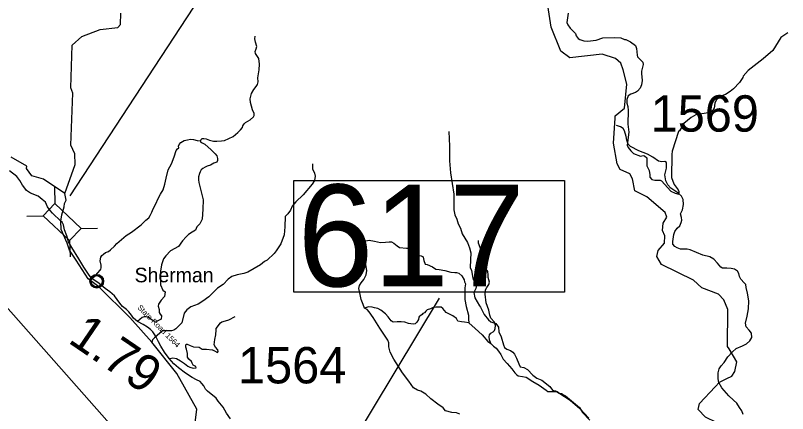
# Model space of a CAD drawing. Extents: x 1248089 to 1457196, y 820910 to 988753.
# Drawn here: x 1308265 to 1318874, y 948203 to 953678 of the extents above; entities that cross this region are included whole.
import ezdxf

# ---------------------------------------------------------------- set-up
doc = ezdxf.new("R2010")
doc.units = 0
for name, color, linetype in [('Exist Civil Demographics Community CELL', 7, 'Continuous'), ('Exist Civil Demographics Community Label', 7, 'Continuous'), ('Exist Hydrographic Creek Single Shore', 7, 'Continuous'), ('Exist Hydrographic Misc Water Feature', 7, 'Continuous'), ('Exist Road Non-System Type 51', 7, 'Continuous'), ('Exist Road Secondary Structure Standard Bridge CELL', 7, 'Continuous'), ('Exist Road Secondary Structure Standard Bridge Number Label', 7, 'Continuous'), ('Exist Road Secondary Type 10 Attributed', 7, 'Continuous'), ('Exist Road Secondary Type 51 Attributed', 7, 'Continuous'), ('Exist Road Secondary Type 51 Label', 7, 'Continuous'), ('Prop GRAU CAT1 Cell', 7, 'Continuous'), ('Prop Lane Lines', 7, 'Continuous')]:
    doc.layers.add(name, color=color, linetype=linetype)

msp = doc.modelspace()

# ---------------------------------------------------------------- linework, layer by layer
at = {"layer": 'Exist Civil Demographics Community CELL'}
msp.add_lwpolyline([(1309304, 950035), (1309305, 950041), (1309307, 950047), (1309310, 950055), (1309313, 950060), (1309316, 950066), (1309320, 950071), (1309324, 950075), (1309328, 950080), (1309334, 950085), (1309339, 950088), (1309344, 950091), (1309349, 950094), (1309355, 950096), (1309360, 950098), (1309365, 950099), (1309369, 950100), (1309374, 950100), (1309380, 950101), (1309384, 950101), (1309390, 950100), (1309395, 950100), (1309400, 950099), (1309405, 950097), (1309410, 950095), (1309417, 950092), (1309423, 950089), (1309428, 950085), (1309433, 950081), (1309436, 950078), (1309441, 950074), (1309444, 950069), (1309448, 950064), (1309451, 950059), (1309453, 950054), (1309455, 950049), (1309457, 950044), (1309458, 950040), (1309459, 950034), (1309460, 950029), (1309460, 950023), (1309460, 950017), (1309459, 950011), (1309458, 950006), (1309457, 950000), (1309455, 949994), (1309452, 949989), (1309449, 949983), (1309446, 949978), (1309443, 949973), (1309438, 949968), (1309433, 949963), (1309428, 949959), (1309423, 949956), (1309419, 949953), (1309412, 949950), (1309405, 949947), (1309399, 949946), (1309392, 949944), (1309388, 949944), (1309383, 949944), (1309378, 949944), (1309373, 949944), (1309368, 949945), (1309362, 949946), (1309357, 949947), (1309352, 949949), (1309347, 949951), (1309344, 949954), (1309337, 949958), (1309331, 949962), (1309326, 949966), (1309322, 949971), (1309319, 949975), (1309316, 949979), (1309312, 949986), (1309310, 949990), (1309308, 949994), (1309306, 950002), (1309304, 950009), (1309303, 950014), (1309303, 950021), (1309303, 950025), (1309303, 950032)], close=True, dxfattribs=at)
for centre, radius in [((1309382, 950023), 94.3), ((1309381, 950023), 76.7)]:
    msp.add_circle(centre, radius, dxfattribs=at)
at = {"layer": 'Exist Hydrographic Creek Single Shore'}
for points in [[(1316504, 952267), (1316507, 952297), (1316634, 952403), (1316667, 952733), (1316613, 952928), (1316582, 953021), (1316508, 953088), (1316326, 953144), (1315883, 953094), (1315759, 953188), (1315625, 953519), (1315560, 953937)], [(1318070, 949093), (1318051, 949124), (1318054, 949633), (1317999, 949769), (1317926, 949845), (1317694, 949932), (1317580, 950036), (1317143, 950255), (1317079, 950365), (1317097, 950446), (1317183, 950547), (1317186, 950645), (1317154, 950721), (1317164, 950823), (1317217, 950904), (1317193, 950970), (1316939, 951185), (1316775, 951264), (1316745, 951432), (1316705, 951498), (1316573, 951560), (1316533, 951636), (1316481, 951923), (1316504, 952267)], [(1308944, 951228), (1308649, 951428), (1308492, 951473), (1308419, 951573), (1308420, 951606), (1308206, 951729)], [(1308887, 950849), (1308902, 950934), (1308935, 951044), (1308941, 951092), (1308964, 951139), (1308944, 951228)], [(1309262, 950054), (1309098, 950312), (1309007, 950452), (1308974, 950547), (1308892, 950733), (1308887, 950849)], [(1311047, 947831), (1310858, 948058), (1310733, 948077), (1310757, 948262), (1310481, 948756), (1310139, 949185), (1309835, 949522), (1309411, 949947), (1309262, 950054)], [(1317921, 947117), (1317896, 947134), (1317947, 947534), (1318087, 947807), (1318114, 947915), (1318050, 948008), (1317745, 948155), (1317647, 948259), (1317665, 948340), (1317879, 948570), (1317939, 948634), (1318041, 948683), (1318108, 948716), (1318151, 948781), (1318179, 948915), (1318070, 949093)]]:
    msp.add_lwpolyline(points, dxfattribs=at)
at = {"layer": 'Exist Hydrographic Misc Water Feature'}
for points in [[(1308944, 951228), (1309087, 951626), (1309082, 951773), (1309027, 951893), (1309052, 952611), (1309028, 952684), (1309042, 953268), (1309178, 953390), (1309431, 953483), (1309673, 953511), (1309707, 953553), (1309711, 953711)], [(1315858, 953711), (1315841, 953580), (1315853, 953548), (1315888, 953503), (1315962, 953429), (1315969, 953397), (1315998, 953360), (1316018, 953347), (1316074, 953330), (1316126, 953323), (1316246, 953340), (1316337, 953372), (1316501, 953376), (1316581, 953370), (1316635, 953347), (1316654, 953346), (1316718, 953317), (1316785, 953263), (1316800, 953223), (1316806, 953134), (1316811, 953111), (1316885, 953037), (1316889, 953005), (1316867, 952913), (1316866, 952881), (1316877, 952783), (1316868, 952723), (1316851, 952676), (1316814, 952636), (1316786, 952617), (1316719, 952595), (1316686, 952573), (1316665, 952522), (1316664, 952473), (1316679, 952425), (1316686, 952373), (1316679, 952181), (1316691, 952071), (1316671, 951895), (1316686, 951862), (1316719, 951818), (1316758, 951781), (1316853, 951742), (1316890, 951752), (1316909, 951747), (1316941, 951718), (1316942, 951608), (1316971, 951544), (1316981, 951484), (1316981, 951452), (1317008, 951422), (1317052, 951412), (1317124, 951414), (1317144, 951402), (1317271, 951263), (1317330, 951233), (1317382, 951220)], [(1318880, 953438), (1318783, 953373), (1318673, 953197), (1318540, 953082), (1318332, 952921), (1318266, 952844), (1318260, 952826), (1318214, 952756), (1318132, 952671), (1318087, 952633), (1318020, 952592), (1317959, 952566), (1317902, 952521), (1317898, 952522), (1317873, 952471), (1317867, 952403), (1317847, 952370), (1317820, 952347), (1317756, 952332), (1317667, 952322), (1317615, 952309), (1317550, 952275), (1317448, 952193), (1317388, 952093), (1317376, 952081), (1317287, 951813), (1317282, 951765), (1317281, 951451), (1317296, 951398), (1317315, 951354), (1317371, 951282), (1317382, 951258), (1317382, 951220)], [(1314219, 952081), (1314228, 951879), (1314227, 951679), (1314242, 951514), (1314289, 951220), (1314290, 951003), (1314304, 950934), (1314329, 950878), (1314347, 950814), (1314378, 950752), (1314404, 950676), (1314475, 950554), (1314506, 950481), (1314524, 950413), (1314516, 950315), (1314514, 950211), (1314529, 950171), (1314548, 950066), (1314556, 950046), (1314583, 950010), (1314598, 949965), (1314593, 949922), (1314562, 949870), (1314576, 949795), (1314641, 949684), (1314657, 949668), (1314705, 949566), (1314763, 949493), (1314798, 949464), (1314866, 949443), (1314901, 949389), (1314909, 949325), (1314940, 949260), (1314969, 949147), (1314986, 949112), (1315018, 949087), (1315065, 949069), (1315101, 949049), (1315124, 949020), (1315151, 948967), (1315181, 948887), (1315202, 948846), (1315250, 948837), (1315301, 948808), (1315372, 948732), (1315431, 948691), (1315498, 948661), (1315606, 948575), (1315645, 948526), (1315685, 948517), (1315736, 948485), (1315768, 948479)], [(1314219, 952081), (1314228, 951879), (1314227, 951679), (1314242, 951514), (1314289, 951220), (1314290, 951003), (1314304, 950934), (1314329, 950878), (1314347, 950814), (1314378, 950752), (1314404, 950676), (1314475, 950554), (1314506, 950481), (1314524, 950413), (1314516, 950315), (1314514, 950211), (1314529, 950171), (1314548, 950066), (1314556, 950046), (1314583, 950010), (1314598, 949965), (1314593, 949922), (1314562, 949870), (1314576, 949795), (1314641, 949684), (1314657, 949668), (1314705, 949566), (1314763, 949493), (1314798, 949464), (1314866, 949443), (1314901, 949389), (1314909, 949325), (1314940, 949260), (1314969, 949147), (1314986, 949112), (1315018, 949087), (1315065, 949069), (1315101, 949049), (1315124, 949020), (1315151, 948967), (1315181, 948887), (1315202, 948846), (1315250, 948837), (1315301, 948808), (1315372, 948732), (1315431, 948691), (1315498, 948661), (1315606, 948575), (1315645, 948526), (1315685, 948517), (1315736, 948485), (1315768, 948479)], [(1312348, 951637), (1312348, 951568), (1312375, 951510), (1312382, 951470), (1312372, 951406), (1312341, 951359), (1312218, 951212), (1312117, 951114), (1312068, 951054), (1312042, 950998), (1312009, 950951), (1311972, 950911), (1311967, 950773), (1311957, 950662), (1311912, 950539), (1311849, 950442), (1311820, 950403), (1311724, 950313), (1311688, 950296), (1311631, 950249), (1311460, 950147), (1311402, 950128), (1311313, 950110), (1311237, 950086), (1311188, 950051), (1311118, 949980), (1311041, 949928), (1310920, 949809), (1310838, 949747), (1310774, 949708), (1310677, 949669), (1310618, 949630), (1310585, 949583), (1310553, 949449), (1310469, 949367), (1310441, 949352), (1310409, 949343), (1310285, 949341), (1310174, 949246), (1310150, 949218), (1310139, 949185)], [(1315768, 948479), (1315776, 948476), (1315788, 948465), (1315823, 948447), (1316014, 948287), (1316056, 948218), (1316158, 948113)]]:
    msp.add_lwpolyline(points, dxfattribs=at)
at = {"layer": 'Exist Road Non-System Type 51'}
for points in [[(1310807, 951953), (1310811, 951969), (1310829, 951987), (1310855, 951987), (1310884, 951982), (1310933, 951963), (1310984, 951949), (1311031, 951948), (1311094, 951953), (1311137, 951958), (1311195, 951984), (1311258, 952014), (1311319, 952067), (1311356, 952103), (1311383, 952138), (1311391, 952159), (1311406, 952186), (1311427, 952208), (1311488, 952242), (1311537, 952284), (1311545, 952303), (1311545, 952331), (1311524, 952379), (1311495, 952482), (1311489, 952531), (1311508, 952603), (1311539, 952659), (1311571, 952702), (1311591, 952730), (1311600, 952763), (1311594, 952820), (1311606, 952874), (1311613, 952931), (1311618, 953009), (1311609, 953085), (1311564, 953155), (1311557, 953184), (1311571, 953221), (1311581, 953252), (1311565, 953310), (1311556, 953355), (1311557, 953395)], [(1309313, 950061), (1309330, 950069), (1309366, 950101), (1309427, 950173), (1309440, 950189), (1309444, 950207), (1309442, 950242), (1309431, 950303), (1309436, 950355), (1309451, 950377), (1309474, 950396), (1309503, 950416), (1309542, 950430), (1309572, 950454), (1309624, 950506), (1309658, 950542), (1309784, 950653), (1309861, 950697), (1309991, 950799), (1310056, 950861), (1310097, 950893), (1310118, 950926), (1310138, 950971), (1310158, 951020), (1310195, 951089), (1310228, 951162), (1310256, 951219), (1310293, 951280), (1310317, 951358), (1310338, 951439), (1310362, 951554), (1310407, 951639), (1310448, 951733), (1310472, 951819), (1310491, 951843), (1310510, 951858), (1310507, 951880), (1310515, 951904), (1310537, 951930), (1310560, 951946), (1310584, 951956), (1310628, 951967), (1310671, 951976), (1310712, 951973), (1310764, 951960), (1310807, 951953)], [(1310807, 951953), (1310808, 951942), (1310822, 951929), (1310869, 951908), (1310954, 951831), (1311008, 951777), (1311030, 951747), (1311039, 951710), (1311043, 951683), (1311030, 951661), (1310993, 951648), (1310944, 951618), (1310898, 951603), (1310871, 951592), (1310838, 951573), (1310819, 951557), (1310805, 951528), (1310795, 951504), (1310779, 951459), (1310779, 951419), (1310785, 951381), (1310846, 951144)], [(1310846, 951144), (1310840, 951012), (1310831, 950875), (1310797, 950814), (1310757, 950769), (1310737, 950724), (1310692, 950696), (1310643, 950667), (1310611, 950635), (1310562, 950578), (1310505, 950500), (1310395, 950439), (1310330, 950370), (1310301, 950329), (1310273, 950247), (1310260, 950162), (1310260, 950035), (1310260, 949974), (1310289, 949901), (1310321, 949876), (1310313, 949815), (1310269, 949762), (1310232, 949709), (1310228, 949678), (1310239, 949636), (1310241, 949591), (1310254, 949568), (1310270, 949547), (1310266, 949500), (1310259, 949497), (1310248, 949490), (1310205, 949470), (1310167, 949475), (1310117, 949506), (1310083, 949527), (1310055, 949532), (1310035, 949531), (1310004, 949524), (1309941, 949471)], [(1314371, 948197), (1314326, 948213), (1314263, 948217), (1314175, 948242), (1314143, 948283), (1314067, 948330), (1313972, 948407), (1313902, 948472), (1313837, 948511), (1313789, 948524), (1313735, 948556), (1313672, 948648), (1313584, 948761), (1313465, 948949), (1313415, 949049), (1313395, 949123), (1313395, 949177), (1313382, 949211), (1313271, 949378), (1313179, 949525), (1313127, 949602), (1313098, 949634), (1313062, 949654), (1313044, 949704), (1313017, 949772), (1312999, 949864), (1312983, 949925), (1312992, 949966), (1313014, 950002), (1313053, 950047), (1313082, 950110), (1313091, 950169), (1313077, 950275), (1313048, 950370), (1313028, 950399), (1313026, 950445), (1313026, 950477), (1313037, 950522), (1313059, 950558), (1313080, 950579), (1313125, 950588), (1313197, 950572), (1313280, 950556), (1313348, 950558), (1313398, 950563), (1313434, 950565), (1313465, 950545), (1313508, 950511), (1313542, 950486), (1313637, 950477), (1313695, 950477), (1313761, 950452)], [(1314796, 949167), (1314777, 949219), (1314775, 949256), (1314779, 949287), (1314799, 949307), (1314831, 949326), (1314847, 949346), (1314858, 949371), (1314863, 949414), (1314849, 949459), (1314797, 949517), (1314781, 949554), (1314770, 949626), (1314732, 949725), (1314721, 949847), (1314725, 949903), (1314743, 949937), (1314770, 949976), (1314777, 950012), (1314761, 950073), (1314759, 950109), (1314757, 950157), (1314734, 950190), (1314705, 950227), (1314687, 950274), (1314687, 950308), (1314689, 950362), (1314662, 950452), (1314626, 950547), (1314626, 950583)], [(1313761, 950452), (1313768, 950425), (1313786, 950400), (1313801, 950375), (1313838, 950373), (1313867, 950360), (1313869, 950353), (1313878, 950308), (1313896, 950256), (1313921, 950251), (1313995, 950220), (1314043, 950188), (1314088, 950186), (1314165, 950170), (1314248, 950147), (1314302, 950145), (1314327, 950145), (1314356, 950132), (1314397, 950098), (1314430, 950044), (1314436, 950015), (1314450, 949988), (1314441, 949932), (1314439, 949866), (1314441, 949771), (1314457, 949674), (1314488, 949555), (1314491, 949503), (1314495, 949453)], [(1314495, 949453), (1314436, 949458), (1314394, 949464), (1314344, 949473), (1314324, 949510), (1314274, 949546), (1314231, 949568), (1314182, 949595), (1314139, 949647), (1314116, 949665), (1314089, 949668), (1314048, 949665), (1313997, 949656), (1313967, 949645), (1313922, 949629), (1313902, 949613), (1313886, 949589), (1313861, 949580), (1313852, 949566), (1313836, 949550), (1313818, 949543), (1313807, 949528), (1313803, 949498), (1313780, 949460), (1313758, 949437), (1313728, 949433), (1313667, 949440), (1313615, 949462), (1313564, 949464), (1313509, 949464), (1313455, 949462), (1313427, 949479), (1313384, 949535), (1313348, 949576), (1313287, 949623), (1313244, 949650), (1313199, 949659), (1313167, 949666), (1313115, 949671), (1313062, 949654)], [(1310377, 948962), (1310408, 948964), (1310426, 948969), (1310479, 948960), (1310531, 948929), (1310586, 948892), (1310634, 948857), (1310663, 948841), (1310709, 948828), (1310746, 948833), (1310742, 948850), (1310707, 948868), (1310691, 948896), (1310683, 948921), (1310646, 948953), (1310628, 948977), (1310628, 949030), (1310613, 949089), (1310604, 949116), (1310604, 949136), (1310610, 949157), (1310624, 949158), (1310665, 949140), (1310713, 949122), (1310790, 949114), (1310830, 949090), (1310889, 949087), (1310968, 949079), (1310973, 949079), (1310999, 949068), (1311039, 949044), (1311052, 949056), (1311047, 949081), (1311012, 949116), (1310997, 949149), (1311006, 949221), (1311017, 949287), (1311021, 949355), (1311025, 949371), (1311041, 949397), (1311063, 949427), (1311083, 949450), (1311103, 949463), (1311151, 949476), (1311199, 949494), (1311283, 949538)], [(1314495, 949453), (1314581, 949373), (1314678, 949285), (1314755, 949192), (1314796, 949167)], [(1314796, 949167), (1314833, 949130), (1314869, 949103), (1314900, 949060), (1314934, 949015), (1314966, 948950), (1315022, 948891), (1315085, 948819), (1315128, 948762), (1315148, 948740), (1315173, 948724), (1315234, 948715), (1315281, 948704), (1315372, 948645), (1315462, 948595), (1315557, 948525), (1315581, 948507), (1315638, 948507), (1315710, 948505), (1315744, 948478), (1315886, 948388), (1316021, 948272), (1316143, 948142)]]:
    msp.add_lwpolyline(points, dxfattribs=at)
at = {"layer": 'Exist Road Secondary Structure Standard Bridge CELL'}
for p, q in [((1308801, 951318), (1308807, 951091)), ((1308421, 950918), (1308647, 950924)), ((1309165, 950749), (1309392, 950754)), ((1309009, 950585), (1309015, 950358))]:
    msp.add_line(p, q, dxfattribs=at)
msp.add_lwpolyline([(1308807, 951091), (1309166, 950749), (1309006, 950582), (1308647, 950924)], close=True, dxfattribs=at)
at = {"layer": 'Exist Road Secondary Structure Standard Bridge Number Label'}
msp.add_line((1309019, 951197), (1312285, 956192), dxfattribs=at)
for points in [[(1311436, 945141), (1311012, 946414), (1306982, 950975), (1306487, 954475)], [(1311311, 947403), (1311959, 947293), (1312875, 947766), (1314091, 949788)]]:
    msp.add_lwpolyline(points, dxfattribs=at)
msp.add_lwpolyline([(1312091, 951409), (1315807, 951409), (1315807, 949873), (1312091, 949873)], close=True, dxfattribs=at)
at = {"layer": 'Exist Road Secondary Type 10 Attributed'}
for points in [[(1318065, 948448), (1317973, 948557), (1317932, 948629), (1317919, 948679), (1317920, 948763), (1317935, 948819), (1317961, 948858), (1318005, 948904), (1318055, 948981), (1318116, 949054), (1318170, 949099), (1318256, 949135), (1318310, 949163), (1318355, 949204), (1318381, 949251), (1318379, 949307), (1318346, 949351), (1318307, 949394), (1318294, 949447), (1318317, 949544), (1318337, 949643), (1318340, 949753), (1318322, 949860), (1318304, 949936), (1318299, 949977), (1318276, 950002), (1318232, 950053), (1318216, 950086), (1318206, 950130), (1318187, 950161), (1318143, 950191), (1318099, 950199), (1318041, 950202), (1317979, 950203), (1317955, 950218), (1317912, 950273), (1317861, 950326), (1317804, 950358), (1317711, 950383), (1317537, 950456), (1317493, 950464), (1317403, 950464), (1317358, 950481), (1317323, 950502), (1317298, 950531), (1317300, 950570), (1317311, 950667), (1317326, 950709), (1317359, 950753), (1317394, 950787), (1317414, 950829), (1317423, 950862), (1317415, 950898), (1317402, 950950), (1317430, 951006), (1317443, 951077), (1317438, 951149), (1317418, 951191), (1317368, 951238), (1317268, 951302), (1317230, 951347), (1317203, 951405), (1317189, 951485), (1317209, 951578), (1317212, 951620), (1317209, 951655), (1317190, 951668), (1317146, 951667), (1317100, 951674), (1317021, 951728), (1316950, 951772), (1316831, 951816), (1316718, 951876), (1316684, 951910), (1316665, 951963), (1316658, 952015), (1316635, 952089), (1316616, 952122), (1316577, 952145), (1316524, 952163)], [(1318264, 948191), (1318244, 948240), (1318214, 948288), (1318176, 948346), (1318131, 948385), (1318065, 948448)]]:
    msp.add_lwpolyline(points, dxfattribs=at)
at = {"layer": 'Exist Road Secondary Type 51 Attributed'}
for points in [[(1308887, 950849), (1308772, 950958), (1308740, 950996), (1308706, 951047), (1308676, 951109), (1308634, 951145), (1308575, 951194), (1308473, 951236), (1308419, 951270), (1308393, 951302), (1308364, 951346), (1308324, 951410), (1308285, 951461), (1308184, 951541)], [(1311221, 948130), (1311166, 948210), (1311117, 948293), (1311052, 948374), (1311024, 948414), (1310994, 948439), (1310954, 948469), (1310903, 948509), (1310877, 948540), (1310855, 948586), (1310828, 948616), (1310802, 948644), (1310752, 948665), (1310694, 948697), (1310601, 948760), (1310504, 948834), (1310440, 948889), (1310377, 948962), (1310315, 949048), (1310261, 949132), (1310231, 949189), (1310189, 949274), (1310153, 949327), (1310119, 949361), (1310081, 949393), (1310022, 949427), (1309941, 949471), (1309889, 949517), (1309861, 949557), (1309823, 949604), (1309789, 949634), (1309734, 949676), (1309698, 949723), (1309662, 949771), (1309626, 949822), (1309561, 949877), (1309497, 949922), (1309414, 949990), (1309313, 950061), (1309277, 950108), (1309203, 950218), (1309135, 950330), (1309040, 950485), (1308994, 950564), (1308971, 950645), (1308941, 950732), (1308926, 950797), (1308905, 950833), (1308887, 950849)]]:
    msp.add_lwpolyline(points, dxfattribs=at)

# ---------------------------------------------------------------- texts
at = {"layer": 'Exist Civil Demographics Community Label'}
msp.add_text('Sherman', height=200, dxfattribs=at).set_placement((1309902, 950008))
at = {"layer": 'Exist Road Secondary Structure Standard Bridge Number Label'}
msp.add_text('617', height=1400, dxfattribs=at).set_placement((1312141, 949952))
at = {"layer": 'Exist Road Secondary Type 51 Label'}
msp.add_text('State Road 1564', height=75, rotation=314.9302, dxfattribs=at).set_placement((1309934, 949655))
at = {"layer": 'Prop GRAU CAT1 Cell'}
msp.add_text('1.79', height=500, rotation=325.6899, dxfattribs=at).set_placement((1308971, 949190))
at = {"layer": 'Prop Lane Lines'}
for s, p in [('1569', (1316993, 952080)), ('1564', (1311324, 948618))]:
    msp.add_text(s, height=500, dxfattribs=at).set_placement(p)

doc.saveas('drawing.dxf')
